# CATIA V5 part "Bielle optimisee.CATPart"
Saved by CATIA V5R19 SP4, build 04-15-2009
Part number: Bielle
Bounding box of the stored display mesh (mm): x 20 to 24, y 12.808 to 97.847, z 197.254 to 685.345
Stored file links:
  D:\Documents\Scolaire\MM2\CFAO\Brevet\MODELE CATIA\Squelette\Bielle optimisee.CATPart
  D:\Documents\Scolaire\MM2\IAO\Squelette\Product1.CATProduct
  D:\Documents\Scolaire\MM2\IAO\Squelette\Squelette de base.CATPart
  D:\Documents\Scolaire\MM2\IAO\Squelette\Squelette coulisso.CATPart
  D:\Documents\Scolaire\MM2\IAO\Squelette\Squelette  bielle.CATPart
  D:\Documents\Scolaire\MM2\IAO\Squelette\Squelette bati.CATPart
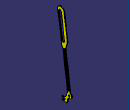
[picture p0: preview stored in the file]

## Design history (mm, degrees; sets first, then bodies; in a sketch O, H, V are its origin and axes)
Parameters
  diam_axe_bielle = 20 mm
External parameters (linked from other documents)
  External.diametre_vilebrequin = 100 mm
Set1
  Sketch1 on Plane1, origin (0, 0, 0), H (0, 1, 0), V (0, 0, 1)
    line L1 (73.4087, 251.8961) -> (43.7125, 474.5265)
    point P2 (43.7125, 474.5265)
    point P3 (92.6235, 228.8572)
    line L2 (92.6235, 228.8572) -> (71.2242, 197.2539)
    point P4 (71.2242, 197.2539)
    line L3 (71.2242, 197.2539) -> (61.6659, 197.2539)
    point P5 (71.2242, 197.2539)
    line L4 (61.6659, 197.2539) -> (53.9096, 199.2539)
    line L5 (53.9096, 199.2539) -> (38.0161, 199.2539)
    line L6 (38.0161, 199.2539) -> (38.0161, 203.2539)
    line L7 (38.0161, 203.2539) -> (58.0161, 203.2539)
    line L8 (58.0161, 203.2539) -> (58.0161, 215.2539)
    line L9 (58.0161, 215.2539) -> (38.0161, 215.2539)
    line L10 (38.0161, 215.2539) -> (38.0161, 219.2539)
    line L11 (38.0161, 219.2539) -> (58.0161, 219.2539)
    point P14 (58.0161, 219.2539)
    point P15 (58.0161, 219.2539)
    point P16 (89.2682, 254.0116)
    point P17 (68.8944, 235.3193)
    line L12 (58.0161, 219.2539) -> (68.8944, 235.3193)
    line L13 (89.2682, 254.0116) -> (59.5721, 476.6419)
    point P18 (59.5721, 476.6419)
    arc A1 centre (26.9896, 660.4039) radius 25 from (51.7701, 663.7093) to (2.2091, 657.0985) ccw
    point P19 (26.9896, 660.4039)
    point P20 (51.7701, 663.7093)
    point P21 (2.2091, 657.0985)
    construction line L14 (8.0576, 657.8786) -> (47.8699, 663.1891)
    line L15 (2.2091, 657.0985) -> (22.0416, 508.4154)
    point P25 (83.0161, 240.3767)
    point P26 (71.6026, 515.0262)
    point P27 (51.7701, 663.7093)
    line L16 (51.7701, 663.7093) -> (71.6026, 515.0262)
    construction line L17 (26.9896, 660.4039) -> (46.8221, 511.7208)
    point P28 (46.8221, 511.7208)
    line L18 (34.9194, 661.4616) -> (54.7519, 512.7785)
    line L19 (38.8923, 510.663) -> (19.0598, 659.3462)
    arc A2 centre (46.8221, 511.7208) radius 8 from (54.7519, 512.7785) to (38.8923, 510.663) cw
    arc A3 centre (26.9896, 660.4039) radius 8 from (19.0598, 659.3462) to (34.9194, 661.4616) cw
    line L20 (22.0416, 508.4154) -> (43.7125, 474.5265)
    line L21 (59.5721, 476.6419) -> (71.6026, 515.0262)
    arc A4 centre (83.0161, 240.3767) radius 15 from (73.4087, 251.8961) to (68.8944, 235.3193) ccw
    point P33 (68.8944, 235.3193)
    arc A5 centre (83.0161, 240.3767) radius 15 from (92.6235, 228.8572) to (89.2682, 254.0116) ccw
    point P34 (92.6235, 228.8572)
    reference projected line E1 (79.6533, 265.5876) -> (37.2843, 583.2248) from Line2
    reference projected point E2 (83.0161, 240.3767) from DatumPoint1
    reference projected line E3 (43.8952, 533.6638) -> (30.6735, 632.7858) from Line3
    construction line L22 (73.4087, 251.8961) -> (89.2682, 254.0116)
    point P35 (89.2682, 254.0116)
    reference projected line E4 (79.6533, 265.5876) -> (37.2843, 583.2248) from Line2
    reference projected line E5 (79.6533, 265.5876) -> (37.2843, 583.2248) from Line2
    reference projected line E6 (79.6533, 265.5876) -> (37.2843, 583.2248) from Line2
    construction line L23 (20.6675, 508.2321) -> (59.2983, 513.3849)
    reference projected line E7 (79.6533, 265.5876) -> (37.2843, 583.2248) from Line2
    axis line L24 (47.3529, 475.0121) -> (57.1098, 476.3135)
    reference projected point E8 (36.9059, 586.0623) from Point3
    radius A1 = 25
    length L15 = 150 {= External.diametre_vilebrequin *1.5}
    length L3 = 9.5583
    length L9 = 20
    length L6 = 4
    length L10 = 4
    distance L17 L18 = 8
    length L19 = 150 {= External.diametre_vilebrequin *1.5}
    radius A4 = 15
    radius A5 = 15
    length L8 = 12
    distance L3 L5 = 2
    angle L21 E6 = 155
    distance E8 L14 = 75 {= External.diametre_vilebrequin *3/4}
    distance L10 P25 = 45
    angle L5 L4 = 165.541
    horizontal: L3 H, L5 H, L7 H, L9 H, L11 H
    vertical: L8 V, L10 V, L6 V
    coincidence: P14 L8, L2 P5, P19 L14, P21 L14, P20 L14, P4 P5, P20 P27, L1 L19, P17 P33, P34 L13, P3 P34, P25 E2, L17 E3, P35 P16, L23 P28, P26 L23, P18 L24, P2 L24, L6 L10, P14 P15
    parallelism: L13 L1, L12 L2, L1 E1, L15 L17, L13 L17, L24 L23, L15 L16
    tangency: A2 L18, A3 L18, A2 L19, A3 L19
    perpendicularity: L22 E4, L22 E5, L14 L17, L23 E7
Set2
  Plane1: linked copy from another document
  Point1: linked copy from another document
  Line1: linked copy from another document
  Line2: linked copy from another document
  DatumPoint1: linked copy from another document
  Line3: linked copy from another document
  Point2: linked copy from another document
  Point3: linked copy from another document
Body1 (main body)
  Pad1: profile Sketch1, direction (1, 0, 0), length 24, opposite side length -20
  Sketch2 on end face of Pad1, origin (24, 89.5322, 246.498), H (0, 1, 0), V (0, 0, 1)
    point P1 (-6.5161, -6.1213)
    reference projected arc E1 centre (-6.5161, -6.1213) radius 15 from (-16.8434, 4.7574) to (-18.6814, -14.8965) ccw from edge [face of Pad1 from Sketch1.A4 | end face of Pad1]
    concentricity: P1 E1
  Hole1: placed by Sketch2, at (24, 83.0161, 240.3767) direction (-1, 0, 0), diameter 10, through (limit type 3)
  Sketch3 on end face of Pad1, origin (24, 0, 0), H (0, 1, 0), V (0, 0, 1)
    line L1 (-36.4885, 696.3629) -> (9.078, 696.3629)
    line L2 (9.078, 696.3629) -> (43.5695, 437.7817)
    line L3 (43.5695, 437.7817) -> (-36.4885, 437.7817)
    line L4 (-36.4885, 437.7817) -> (-36.4885, 696.3629)
    reference projected line E1 (2.2091, 657.0985) -> (22.0416, 508.4154) from edge [start face of Pad1 | face of Pad1 from Sketch1.L15]
    reference projected line E2 (19.0598, 659.3462) -> (38.8923, 510.663) from edge [face of Pad1 from Sketch1.L19 | start face of Pad1]
    distance L2 E2 = 5
    horizontal: L1 H, L3 H
    vertical: L4 V
    parallelism: L2 E1
  Pocket1: profile Sketch3, direction (-1, 0, 0), through (limit type 3)
  Fillet1: radius 15, on edge [face of Pad1 from Sketch1.A1 | face of Pocket1 from Sketch3.L2]
  Fillet2: radius 30, on edge [face of Pad1 from Sketch1.L16 | face of Pad1 from Sketch1.L21]
  Sketch4 on end face of Pad1, origin (24, 0, 0), H (0, 1, 0), V (0, 0, 1)
    line L1 (70.0696, 195.8844) -> (76.2911, 229.6605)
    point P1 (70.0696, 195.8844)
    point P2 (76.2911, 229.6605)
    line L2 (76.2911, 229.6605) -> (102.9487, 229.6605)
    point P3 (76.2911, 229.6605)
    point P4 (102.9487, 229.6605)
    line L3 (102.9487, 229.6605) -> (82.8063, 195.3795)
    point P5 (102.9487, 229.6605)
    line L4 (82.8063, 195.3795) -> (70.0696, 195.8844)
    point P7 (70.0696, 195.8844)
    coincidence: P3 L1, P5 L2, L4 P1, P4 P5, P3 P2, P7 P1
    horizontal: L2 H
  Pocket2: profile Sketch4, direction (-1, 0, 0), through (limit type 3)
  Fillet3: radius 5, on edge [face of Pocket2 from Sketch4.L1 | face of Pocket2 from Sketch4.L2]
  Sketch5 on end face of Pad1, origin (24, 0, 0), H (0, 1, 0), V (0, 0, 1)
    line L1 (48.6686, 475.1876) -> (77.0426, 262.4694)
    point P1 (48.6686, 475.1876)
    point P2 (77.0426, 262.4694)
    line L2 (54.616, 475.9809) -> (49.0252, 475.2351)
    reference projected line E1 (45.1302, 463.8981) -> (73.4087, 251.8961) from edge [start face of Pad1 | face of Pad1 from Sketch1.L1]
    reference projected line E2 (45.1302, 463.8981) -> (73.4087, 251.8961) from edge [start face of Pad1 | face of Pad1 from Sketch1.L1]
    reference projected line E3 (45.1302, 463.8981) -> (73.4087, 251.8961) from edge [start face of Pad1 | face of Pad1 from Sketch1.L1]
    reference projected point E4 (43.7125, 474.5265) from vertex [face of Pad1 from Sketch1.L1 | start face of Pad1 | face of Pad1 from Sketch1.L20]
    line L3 (54.616, 475.9809) -> (82.99, 263.2627)
    point P5 (82.99, 263.2627)
    line L4 (77.0426, 262.4694) -> (82.99, 263.2627)
    point P6 (77.0426, 262.4694)
    point P7 (82.99, 263.2627)
    reference projected line E5 (89.2682, 254.0116) -> (59.5721, 476.6419) from edge [start face of Pad1 | face of Pad1 from Sketch1.L13]
    reference projected line E6 (89.2682, 254.0116) -> (59.5721, 476.6419) from edge [start face of Pad1 | face of Pad1 from Sketch1.L13]
    reference projected point E7 (73.4087, 251.8961) from vertex [face of Pad1 from Sketch1.L1 | start face of Pad1 | face of Pad1 from Sketch1.A4]
    distance E3 L1 = 5
    distance L2 E4 = 0
    distance L3 E6 = 5
    distance L4 E7 = 10
    coincidence: L2 P1, P2 P6, P7 P5
    perpendicularity: L2 E1, L4 L3
    parallelism: L1 E2, L3 E5
  Pocket3: profile Sketch5, direction (-1, 0, 0), through (limit type 3)
  Chamfer1: length 5, angle 45, on edge [face of Pad1 from Sketch1.L11 | face of Pad1 from Sketch1.L12]
  Chamfer2: length 5, angle 45, on edge [face of Pad1 from Sketch1.L7 | face of Pad1 from Sketch1.L8]
  Fillet4: radius 2, on edge [face of Chamfer1 | face of Pad1 from Sketch1.L11]
  Fillet5: radius 1, on edge [face of Pad1 from Sketch1.L12 | face of Pad1 from Sketch1.A4]
  Fillet6: radius 5, on edge [face of Chamfer2 | face of Pad1 from Sketch1.L7]
Relations
  Hole1.Depth = diam_axe_bielle (deactivated)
